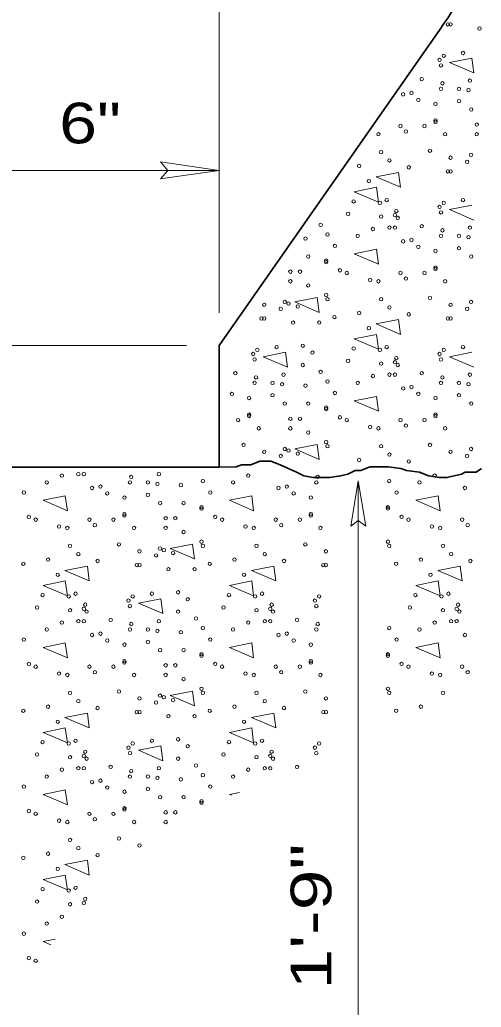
# Model space of a CAD drawing. Extents: x -16.43 to -9.36, y -8.57 to 1.26.
# Drawn here: x -14.571 to -13.889, y -2.302 to -0.843 of the extents above; entities that cross this region are included whole.
import ezdxf
from ezdxf.enums import TextEntityAlignment as Align

# ---------------------------------------------------------------- set-up
doc = ezdxf.new("R2010")
doc.units = 0
doc.header["$LTSCALE"] = 0.024
for name, color, linetype, lineweight in [('1', 7, 'Continuous', 35), ('10', 7, 'Continuous', 13), ('12', 7, 'Continuous', 53), ('6', 7, 'Continuous', 13)]:
    doc.layers.add(name, color=color, linetype=linetype, lineweight=lineweight)

msp = doc.modelspace()

# ---------------------------------------------------------------- linework, layer by layer
at = {"layer": '1'}
msp.add_line((-14.2765, -1.504), (-14.66667, -1.504), dxfattribs=at)
for points in [[(-14.2765, -1.504), (-14.2765, -1.324), (-13.9495, -0.85667)], [(-14.2765, -1.504), (-14.25133, -1.50333), (-14.24317, -1.50067), (-14.22967, -1.50067), (-14.21617, -1.49517), (-14.19983, -1.49517), (-14.18633, -1.50067), (-14.16183, -1.5115), (-14.151, -1.51683), (-14.1375, -1.5195), (-14.12933, -1.5195), (-14.113, -1.5195), (-14.09683, -1.51683), (-14.086, -1.51417), (-14.07517, -1.50867), (-14.067, -1.50867), (-14.05333, -1.50333), (-14.03983, -1.50333), (-14.02633, -1.50333), (-14.00733, -1.506), (-13.99917, -1.50867), (-13.98017, -1.5115), (-13.96667, -1.51683), (-13.95033, -1.5195), (-13.9395, -1.5195), (-13.92867, -1.51683), (-13.91783, -1.51417), (-13.9125, -1.5115), (-13.89617, -1.5115), (-13.888, -1.506)]]:
    msp.add_lwpolyline(points, dxfattribs=at)
msp.add_arc((-14.44102, -0.51249), 0.6001, 325.00798, 355.23636, dxfattribs=at)
at = {"layer": '10'}
for p, q in [((-14.2765, -1.276), (-14.2765, -0.49767)), ((-14.66667, -1.0655), (-14.2765, -1.0655)), ((-14.363, -1.05283), (-14.2765, -1.0655)), ((-14.363, -1.05283), (-14.35217, -1.0655)), ((-14.363, -1.078), (-14.2765, -1.0655)), ((-14.363, -1.078), (-14.35217, -1.0655)), ((-14.3245, -1.324), (-14.6425, -1.324)), ((-14.08167, -1.59133), (-14.0705, -1.52417)), ((-14.0705, -2.82117), (-14.0705, -1.52417)), ((-14.05933, -1.59133), (-14.0705, -1.52417)), ((-14.08167, -1.59133), (-14.0705, -1.58283)), ((-14.05933, -1.59133), (-14.0705, -1.58283))]:
    msp.add_line(p, q, dxfattribs=at)
at = {"layer": '6'}
for p, q in [((-13.93533, -1.12333), (-13.90233, -1.11683)), ((-13.89933, -1.13867), (-13.93533, -1.12333)), ((-13.93533, -1.34067), (-13.90233, -1.33417)), ((-13.89933, -1.356), (-13.93533, -1.34067)), ((-14.26117, -1.98767), (-14.2465, -1.98467)), ((-14.25817, -1.989), (-14.26117, -1.98767)), ((-14.537, -2.205), (-14.519, -2.2015)), ((-14.5255, -2.21), (-14.537, -2.205))]:
    msp.add_line(p, q, dxfattribs=at)
for points in [[(-13.93533, -0.906), (-13.90233, -0.8995), (-13.89933, -0.92133)], [(-14.04417, -1.075), (-14.01117, -1.0685), (-14.00817, -1.09033)], [(-14.07683, -1.09683), (-14.04367, -1.09033), (-14.04083, -1.11217)], [(-14.07683, -1.1885), (-14.04367, -1.182), (-14.04083, -1.20383)], [(-14.16433, -1.25967), (-14.13133, -1.25317), (-14.12833, -1.27517)], [(-14.04417, -1.29233), (-14.01117, -1.28583), (-14.00817, -1.30767)], [(-14.07683, -1.31417), (-14.04367, -1.30767), (-14.04083, -1.3295)], [(-14.21117, -1.34067), (-14.178, -1.33417), (-14.17517, -1.356)], [(-14.07683, -1.40583), (-14.04367, -1.39933), (-14.04083, -1.42117)], [(-14.16433, -1.477), (-14.13133, -1.4705), (-14.12833, -1.4925)], [(-14.537, -1.553), (-14.504, -1.5465), (-14.501, -1.56833)], [(-14.26117, -1.553), (-14.22817, -1.5465), (-14.22533, -1.56833)], [(-13.9855, -1.553), (-13.95233, -1.5465), (-13.9495, -1.56833)], [(-14.34883, -1.62417), (-14.31567, -1.61767), (-14.31283, -1.63967)], [(-14.5045, -1.65683), (-14.47133, -1.65033), (-14.4685, -1.67217)], [(-14.22867, -1.65683), (-14.19567, -1.65033), (-14.19267, -1.67217)], [(-13.95283, -1.65683), (-13.91983, -1.65033), (-13.91683, -1.67217)], [(-14.537, -1.67867), (-14.504, -1.67217), (-14.501, -1.694)], [(-14.26117, -1.67867), (-14.22817, -1.67217), (-14.22533, -1.694)], [(-13.9855, -1.67867), (-13.95233, -1.67217), (-13.9495, -1.694)], [(-14.39567, -1.70517), (-14.3625, -1.69867), (-14.35967, -1.7205)], [(-14.537, -1.77033), (-14.504, -1.76383), (-14.501, -1.78567)], [(-14.26117, -1.77033), (-14.22817, -1.76383), (-14.22533, -1.78567)], [(-13.9855, -1.77033), (-13.95233, -1.76383), (-13.9495, -1.78567)], [(-14.34883, -1.8415), (-14.31567, -1.835), (-14.31283, -1.857)], [(-14.5045, -1.87417), (-14.47133, -1.86767), (-14.4685, -1.8895)], [(-14.22867, -1.87417), (-14.19567, -1.86767), (-14.19267, -1.8895)], [(-14.537, -1.896), (-14.504, -1.8895), (-14.501, -1.9115)], [(-14.26117, -1.896), (-14.22817, -1.8895), (-14.22533, -1.9115)], [(-14.39567, -1.9225), (-14.3625, -1.916), (-14.35967, -1.938)], [(-14.537, -1.98767), (-14.504, -1.98117), (-14.501, -2.003)], [(-14.5045, -2.0915), (-14.47133, -2.085), (-14.4685, -2.10683)], [(-14.537, -2.11333), (-14.504, -2.10683), (-14.501, -2.12883)]]:
    msp.add_lwpolyline(points, close=True, dxfattribs=at)
for centre in [(-13.93795, -0.84954), (-13.93391, -0.84954), (-13.89114, -0.85562), (-13.91558, -0.89179), (-13.95019, -0.90199), (-13.94407, -0.89587), (-13.94815, -0.91011), (-13.97663, -0.93048), (-13.94611, -0.9366), (-13.90538, -0.93252), (-13.99184, -0.95084), (-13.94815, -0.94472), (-13.92166, -0.94472), (-13.90742, -0.94676), (-14.00408, -0.95288), (-13.98167, -0.961), (-13.92166, -0.96304), (-13.95627, -0.96712), (-13.90334, -0.97528), (-13.95627, -0.99157), (-13.95627, -0.99361), (-14.00812, -0.99969), (-14, -1.00785), (-13.97255, -0.99969), (-13.89522, -0.99765), (-14.04072, -1.01193), (-13.94203, -1.01193), (-13.89522, -1.01193), (-14.03664, -1.03837), (-13.96443, -1.03633), (-14.02444, -1.05062), (-13.93391, -1.04653), (-13.90946, -1.05262), (-13.90358, -1.04237), (-14.06921, -1.05874), (-13.99592, -1.06078), (-13.93795, -1.0669), (-13.93391, -1.0669), (-14.05497, -1.08114), (-14.07737, -1.11119), (-14.02848, -1.10915), (-13.91558, -1.10915), (-14.03868, -1.11323), (-14.01424, -1.12543), (-13.95019, -1.11935), (-13.94407, -1.11323), (-14.08549, -1.12951), (-14.03664, -1.13359), (-14.01628, -1.13155), (-14.0122, -1.13563), (-13.94815, -1.12747), (-14.12622, -1.14579), (-14.04885, -1.15191), (-14.02444, -1.14987), (-14.01628, -1.14987), (-13.97663, -1.14783), (-13.94611, -1.15395), (-13.90538, -1.14987), (-14.14862, -1.16615), (-14.11606, -1.16003), (-14.07125, -1.16207), (-13.99184, -1.16819), (-13.94815, -1.16207), (-13.92166, -1.16207), (-13.90742, -1.16411), (-14.10513, -1.17696), (-14.00408, -1.17023), (-13.98167, -1.17836), (-13.95627, -1.18448), (-13.92166, -1.1804), (-14.14454, -1.19264), (-14.11806, -1.19872), (-13.90334, -1.19264), (-14.11806, -1.20076), (-14.09773, -1.213), (-13.95627, -1.20892), (-13.95627, -1.21096), (-14.17102, -1.215), (-14.15674, -1.215), (-14.08753, -1.21704), (-14.05293, -1.22724), (-14.00812, -1.21704), (-14, -1.2252), (-13.97255, -1.21704), (-14.17102, -1.22928), (-14.14454, -1.23537), (-14.04072, -1.22928), (-13.94203, -1.22928), (-14.11806, -1.24965), (-14.11606, -1.25573), (-14.03664, -1.25573), (-13.96443, -1.25369), (-14.20971, -1.26389), (-14.18527, -1.26997), (-14.17939, -1.25973), (-14.17375, -1.26217), (-14.1601, -1.26653), (-14.02444, -1.26797), (-13.93391, -1.26389), (-13.90946, -1.26997), (-13.90358, -1.25973), (-14.21375, -1.28425), (-14.20971, -1.28425), (-14.10585, -1.28221), (-14.06921, -1.27609), (-13.99592, -1.27813), (-13.93795, -1.28425), (-13.93391, -1.28425), (-14.16694, -1.29033), (-14.12826, -1.29033), (-14.05497, -1.2985), (-14.21987, -1.33058), (-14.19139, -1.3265), (-14.1527, -1.32446), (-14.07737, -1.32854), (-14.03868, -1.33058), (-14.02848, -1.3265), (-13.94407, -1.33058), (-13.91558, -1.3265), (-14.22599, -1.3367), (-14.22395, -1.34482), (-14.13842, -1.33466), (-14.01424, -1.34278), (-13.95019, -1.3367), (-13.94815, -1.34482), (-14.1527, -1.35298), (-14.08549, -1.34686), (-14.03664, -1.35094), (-14.01628, -1.3489), (-14.0122, -1.35298), (-14.25244, -1.36519), (-14.22191, -1.37131), (-14.18119, -1.36723), (-14.12622, -1.36315), (-14.04885, -1.36927), (-14.02444, -1.36723), (-14.01628, -1.36723), (-13.97663, -1.36519), (-13.94611, -1.37131), (-13.90538, -1.36723), (-14.22395, -1.37943), (-14.19747, -1.37943), (-14.18323, -1.38147), (-14.14862, -1.38351), (-14.11606, -1.37739), (-14.07125, -1.37943), (-14.00408, -1.38759), (-13.99184, -1.38555), (-13.94815, -1.37943), (-13.92166, -1.37943), (-13.90742, -1.38147), (-14.25748, -1.39571), (-14.23207, -1.40183), (-14.19747, -1.39775), (-14.10513, -1.39431), (-13.98167, -1.39571), (-13.95627, -1.40183), (-13.92166, -1.39775), (-14.17915, -1.40999), (-14.14454, -1.40999), (-14.11806, -1.41607), (-14.11806, -1.41811), (-13.90334, -1.40999), (-14.23207, -1.42628), (-14.23207, -1.42832), (-14.17102, -1.43236), (-14.15674, -1.43236), (-14.09773, -1.43036), (-13.95627, -1.42628), (-13.95627, -1.42832), (-14.24836, -1.4344), (-14.21783, -1.44664), (-14.17102, -1.44664), (-14.08753, -1.4344), (-14.05293, -1.4446), (-14.04072, -1.44664), (-14.00812, -1.4344), (-14, -1.44256), (-13.97255, -1.4344), (-13.94203, -1.44664), (-14.14454, -1.45272), (-14.24024, -1.47104), (-14.11806, -1.467), (-14.11606, -1.47308), (-14.03664, -1.47308), (-13.96443, -1.47104), (-14.20971, -1.48124), (-14.18527, -1.48733), (-14.17939, -1.47708), (-14.17375, -1.47952), (-14.1601, -1.48388), (-14.02444, -1.48533), (-13.93391, -1.48124), (-13.90946, -1.48733), (-13.90358, -1.47708), (-14.06921, -1.49345), (-13.99592, -1.49549), (-14.50912, -1.51641), (-14.48471, -1.51437), (-14.47655, -1.51437), (-14.40638, -1.51845), (-14.36566, -1.51437), (-14.23331, -1.51641), (-14.13058, -1.51845), (-13.95751, -1.51641), (-14.53152, -1.52657), (-14.46435, -1.53473), (-14.45211, -1.53269), (-14.40842, -1.52657), (-14.38194, -1.52657), (-14.3677, -1.52861), (-14.33309, -1.53065), (-14.30053, -1.52453), (-14.25572, -1.52657), (-14.18855, -1.53473), (-14.17631, -1.53269), (-14.13262, -1.52657), (-14.02472, -1.52453), (-13.97991, -1.52657), (-13.91274, -1.53473), (-14.56541, -1.54145), (-14.44195, -1.54285), (-14.41654, -1.54898), (-14.38194, -1.54489), (-14.2896, -1.54145), (-14.16614, -1.54285), (-14.14074, -1.54898), (-14.0138, -1.54145), (-14.36362, -1.55714), (-14.32901, -1.55714), (-14.30253, -1.56322), (-14.02672, -1.56322), (-14.55801, -1.5775), (-14.41654, -1.57342), (-14.41654, -1.57546), (-14.30253, -1.56526), (-14.2822, -1.5775), (-14.14074, -1.57342), (-14.14074, -1.57546), (-14.02672, -1.56526), (-14.0064, -1.5775), (-14.54781, -1.58154), (-14.5132, -1.59174), (-14.46839, -1.58154), (-14.46027, -1.5897), (-14.43283, -1.58154), (-14.35549, -1.5795), (-14.34121, -1.5795), (-14.272, -1.58154), (-14.2374, -1.59174), (-14.19259, -1.58154), (-14.18447, -1.5897), (-14.15702, -1.58154), (-13.9962, -1.58154), (-13.96159, -1.59174), (-13.91678, -1.58154), (-13.90866, -1.5897), (-14.501, -1.59378), (-14.4023, -1.59378), (-14.35549, -1.59378), (-14.32901, -1.59986), (-14.22519, -1.59378), (-14.1265, -1.59378), (-13.94939, -1.59378), (-14.49692, -1.62023), (-14.42471, -1.61819), (-14.30253, -1.61415), (-14.30053, -1.62023), (-14.22111, -1.62023), (-14.1489, -1.61819), (-14.02672, -1.61415), (-14.02472, -1.62023), (-13.94531, -1.62023), (-14.48471, -1.63247), (-14.39418, -1.62839), (-14.36974, -1.63447), (-14.36386, -1.62423), (-14.35821, -1.62667), (-14.34457, -1.63103), (-14.20891, -1.63247), (-14.11838, -1.62839), (-13.93311, -1.63247), (-14.56613, -1.64671), (-14.52948, -1.64059), (-14.45619, -1.64263), (-14.39822, -1.64875), (-14.39418, -1.64875), (-14.29032, -1.64671), (-14.25368, -1.64059), (-14.18039, -1.64263), (-14.12242, -1.64875), (-14.11838, -1.64875), (-14.01452, -1.64671), (-13.97787, -1.64059), (-13.90458, -1.64263), (-14.51524, -1.66299), (-14.35141, -1.65483), (-14.31273, -1.65483), (-14.23944, -1.66299), (-13.96363, -1.66299), (-14.53764, -1.69304), (-14.49896, -1.69508), (-14.48876, -1.691), (-14.40434, -1.69508), (-14.37586, -1.691), (-14.33717, -1.68896), (-14.26184, -1.69304), (-14.22315, -1.69508), (-14.21295, -1.691), (-14.12854, -1.69508), (-13.98604, -1.69304), (-13.94735, -1.69508), (-13.93715, -1.691), (-14.47451, -1.70728), (-14.41046, -1.7012), (-14.40842, -1.70932), (-14.32289, -1.69916), (-14.19871, -1.70728), (-14.13466, -1.7012), (-14.13262, -1.70932), (-13.92291, -1.70728), (-14.54576, -1.71136), (-14.49692, -1.71544), (-14.47655, -1.7134), (-14.47247, -1.71748), (-14.33717, -1.71748), (-14.26996, -1.71136), (-14.22111, -1.71544), (-14.20075, -1.7134), (-14.19667, -1.71748), (-13.99416, -1.71136), (-13.94531, -1.71544), (-13.92495, -1.7134), (-13.92086, -1.71748), (-14.50912, -1.73376), (-14.48471, -1.73172), (-14.47655, -1.73172), (-14.43691, -1.72968), (-14.40638, -1.73581), (-14.36566, -1.73172), (-14.31069, -1.72764), (-14.23331, -1.73376), (-14.20891, -1.73172), (-14.20075, -1.73172), (-14.1611, -1.72968), (-14.13058, -1.73581), (-13.95751, -1.73376), (-13.93311, -1.73172), (-13.92495, -1.73172), (-14.53152, -1.74393), (-14.46435, -1.75209), (-14.45211, -1.75005), (-14.40842, -1.74393), (-14.38194, -1.74393), (-14.3677, -1.74597), (-14.33309, -1.74801), (-14.30053, -1.74189), (-14.25572, -1.74393), (-14.18855, -1.75209), (-14.17631, -1.75005), (-14.13262, -1.74393), (-14.02472, -1.74189), (-13.97991, -1.74393), (-13.91274, -1.75209), (-14.56541, -1.75881), (-14.44195, -1.76021), (-14.41654, -1.76633), (-14.38194, -1.76225), (-14.2896, -1.75881), (-14.16614, -1.76021), (-14.14074, -1.76633), (-14.0138, -1.75881), (-14.36362, -1.77449), (-14.32901, -1.77449), (-14.30253, -1.78057), (-14.30253, -1.78261), (-14.02672, -1.78057), (-14.02672, -1.78261), (-14.55801, -1.79485), (-14.41654, -1.79077), (-14.41654, -1.79281), (-14.35549, -1.79686), (-14.34121, -1.79686), (-14.2822, -1.79485), (-14.14074, -1.79077), (-14.14074, -1.79281), (-14.0064, -1.79485), (-14.54781, -1.7989), (-14.5132, -1.8091), (-14.501, -1.81114), (-14.46839, -1.7989), (-14.46027, -1.80706), (-14.43283, -1.7989), (-14.4023, -1.81114), (-14.35549, -1.81114), (-14.272, -1.7989), (-14.2374, -1.8091), (-14.22519, -1.81114), (-14.19259, -1.7989), (-14.18447, -1.80706), (-14.15702, -1.7989), (-14.1265, -1.81114), (-13.9962, -1.7989), (-13.96159, -1.8091), (-13.94939, -1.81114), (-13.91678, -1.7989), (-13.90866, -1.80706), (-14.32901, -1.81722), (-14.49692, -1.83758), (-14.42471, -1.83554), (-14.36386, -1.84158), (-14.30253, -1.8315), (-14.30053, -1.83758), (-14.22111, -1.83758), (-14.1489, -1.83554), (-14.02672, -1.8315), (-14.02472, -1.83758), (-13.94531, -1.83758), (-14.48471, -1.84982), (-14.39418, -1.84574), (-14.36974, -1.85182), (-14.35821, -1.84402), (-14.34457, -1.84838), (-14.20891, -1.84982), (-14.11838, -1.84574), (-14.56613, -1.86407), (-14.52948, -1.85794), (-14.45619, -1.85999), (-14.39822, -1.86611), (-14.39418, -1.86611), (-14.29032, -1.86407), (-14.25368, -1.85794), (-14.18039, -1.85999), (-14.12242, -1.86611), (-14.11838, -1.86611), (-14.01452, -1.86407), (-13.97787, -1.85794), (-14.51524, -1.88035), (-14.35141, -1.87219), (-14.31273, -1.87219), (-14.23944, -1.88035), (-14.53764, -1.91039), (-14.49896, -1.91243), (-14.48876, -1.90835), (-14.40434, -1.91243), (-14.37586, -1.90835), (-14.33717, -1.90631), (-14.26184, -1.91039), (-14.22315, -1.91243), (-14.21295, -1.90835), (-14.12854, -1.91243), (-14.54576, -1.92872), (-14.47451, -1.92464), (-14.41046, -1.91855), (-14.40842, -1.92668), (-14.32289, -1.91651), (-14.26996, -1.92872), (-14.19871, -1.92464), (-14.13466, -1.91855), (-14.13262, -1.92668), (-14.49692, -1.9328), (-14.47655, -1.93076), (-14.47247, -1.93484), (-14.33717, -1.93484), (-14.22111, -1.9328), (-14.20075, -1.93076), (-14.19667, -1.93484), (-14.50912, -1.95112), (-14.48471, -1.94908), (-14.47655, -1.94908), (-14.43691, -1.94704), (-14.40638, -1.95316), (-14.36566, -1.94908), (-14.31069, -1.945), (-14.23331, -1.95112), (-14.20891, -1.94908), (-14.20075, -1.94908), (-14.1611, -1.94704), (-14.53152, -1.96128), (-14.46435, -1.96944), (-14.45211, -1.9674), (-14.40842, -1.96128), (-14.38194, -1.96128), (-14.3677, -1.96332), (-14.33309, -1.96536), (-14.30053, -1.95924), (-14.25572, -1.96128), (-14.56541, -1.97616), (-14.44195, -1.97756), (-14.41654, -1.98368), (-14.38194, -1.9796), (-14.2896, -1.97616), (-14.36362, -1.99185), (-14.32901, -1.99185), (-14.30253, -1.99793), (-14.30253, -1.99997), (-14.55801, -2.01221), (-14.54781, -2.01625), (-14.46839, -2.01625), (-14.43283, -2.01625), (-14.41654, -2.00813), (-14.41654, -2.01017), (-14.35549, -2.01421), (-14.34121, -2.01421), (-14.5132, -2.02645), (-14.501, -2.02849), (-14.46027, -2.02441), (-14.4023, -2.02849), (-14.35549, -2.02849), (-14.49692, -2.05494), (-14.42471, -2.0529), (-14.48471, -2.06718), (-14.39418, -2.0631), (-14.56613, -2.08142), (-14.52948, -2.0753), (-14.45619, -2.07734), (-14.51524, -2.0977), (-14.53764, -2.12775), (-14.49896, -2.12979), (-14.48876, -2.12571), (-14.54576, -2.14607), (-14.47655, -2.14811), (-14.47451, -2.14199), (-14.49692, -2.15015), (-14.50912, -2.16847), (-14.53152, -2.17864), (-14.56541, -2.19352), (-14.55801, -2.22956), (-14.54781, -2.2336)]:
    msp.add_circle(centre, 0.00252, dxfattribs=at)

# ---------------------------------------------------------------- texts
at = {"layer": '12', "width": 1.25}
msp.add_text('6"', height=0.06001, dxfattribs=at).set_placement((-14.46725, -1.02533), align=Align.CENTER)
at = {"layer": '12', "width": 1.35}
msp.add_text('1\'-9"', height=0.06001, rotation=90, dxfattribs=at).set_placement((-14.1105, -2.16825), align=Align.CENTER)

doc.saveas('drawing.dxf')
